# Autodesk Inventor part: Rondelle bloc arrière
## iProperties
Shininess: 20.0
Angle Display Precision: 2
Document Length Units: 11269
Document Angle Units: 11279
Document Time Units: 11290
Document Mass Units: 11283
Document Length Units Precision: 3
Document Angle Units Precision: 2
Created: 2002-09
Part Number: Rondelle bloc arrière
Material: Par défaut
Document SubType Name: Modélisation
Designer: administrateur
Density: 0.0
Volumn: 0.0
Area: 0.0
PropertySet Name: Model Information
Control State: 0
Master: False
Checked Out: False
Author: administrateur
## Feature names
1. Base1
